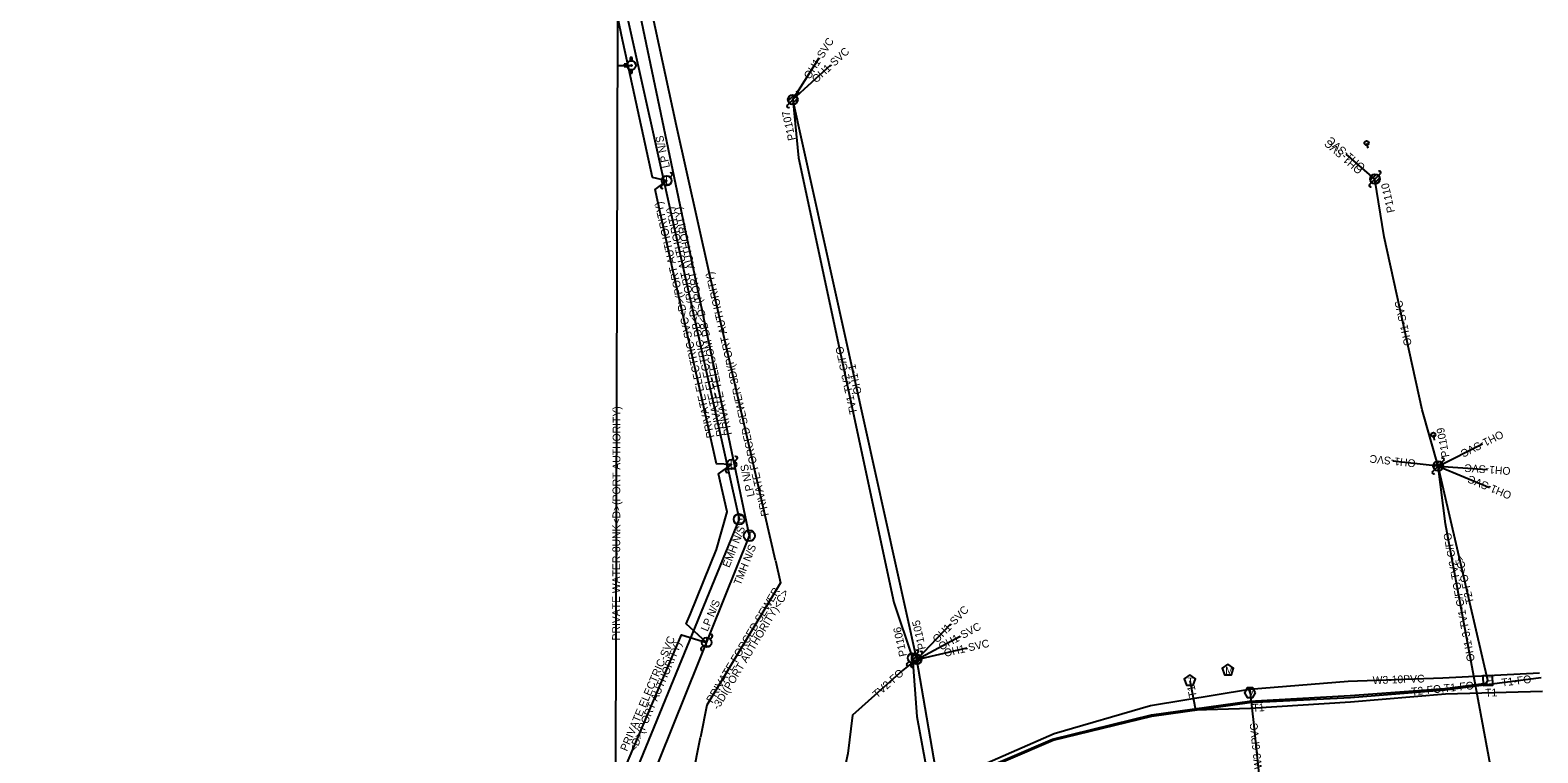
# Model space of a CAD drawing. Extents: x 2336688 to 2352634, y 362473 to 369571.
# Drawn here: x 2345105 to 2345883, y 367110 to 367482 of the extents above; entities that cross this region are included whole.
import ezdxf

# ---------------------------------------------------------------- set-up
doc = ezdxf.new("R2010")
doc.units = 0
for name, color, linetype in [('RD_EX_DV_Prop', 7, 'Continuous'), ('RD_EX_DV_TX_Prop', 7, 'Continuous'), ('RD_EX_RW', 7, 'Continuous'), ('RD_EX_RW_TX', 7, 'Continuous'), ('RD_HC_Data_Tic', 7, 'Continuous'), ('RD_PD_CstnLmt', 7, 'Continuous'), ('RD_PD_Final_TrvlWay', 7, 'Continuous'), ('RD_PD_PatLn4', 7, 'Continuous'), ('RD_SHT_ShtClip', 7, 'Continuous'), ('RD_Sketch1', 7, 'Continuous'), ('RD_Sketch2', 7, 'Continuous'), ('RD_Sketch5', 7, 'Continuous')]:
    doc.layers.add(name, color=color, linetype=linetype)

# ---------------------------------------------------------------- blocks, each defined once
blk = doc.blocks.new('GW')
at = {"layer": 'RD_HC_Data_Tic'}
blk.add_line((0, 0), (0, 5), dxfattribs=at)
blk.add_circle((0, 0), 2, dxfattribs=at)

msp = doc.modelspace()

# ---------------------------------------------------------------- linework, layer by layer
at = {"layer": 'RD_EX_RW_TX'}
msp.add_line((2345857.04, 367146.79), (2345831.39, 367257.27), dxfattribs=at)
for points in [[(2345400.86, 367609.96), (2345400.86, 367580.52), (2345476.19, 367221.38), (2345364.16, 366943.34), (2345117.95, 366720.57)], [(2345560.36, 367158.37), (2345561.17, 367156.84), (2345555.2, 367151.92), (2345529.41, 367128.95), (2345527.05, 367109.15), (2345521, 367081.68), (2345512.82, 367070.16), (2345492.13, 367039.11), (2345457.71, 366999.28), (2345443.39, 366979.23), (2345436.01, 366963.6), (2345427.31, 366951.13), (2345399.42, 366920.61), (2345372.17, 366875.98), (2345340.52, 366834.69)], [(2345399.69, 366921.53), (2345400.81, 366920.91), (2345403.09, 366921.35), (2345436.25, 366953.11), (2345452.55, 366965.66), (2345470.76, 366986.63), (2345499.17, 367023.99), (2345542.57, 367063.95), (2345586.06, 367096.71), (2345632.54, 367116.51), (2345683.64, 367129.17), (2345734.05, 367136.11), (2345786.05, 367139.04), (2345834.85, 367142.6), (2345856.07, 367145.42), (2345857.04, 367146.79)], [(2345400.81, 366920.91), (2345403.21, 366920.71), (2345436.7, 366952.69), (2345453.09, 366965.46), (2345471.44, 366986.29), (2345499.66, 367023.61), (2345543.05, 367063.34), (2345586.52, 367096.12), (2345632.95, 367115.99), (2345683.75, 367128.36), (2345734.17, 367135.46), (2345786.21, 367138.11), (2345835, 367141.95), (2345884.47, 367148.28)], [(2345703.35, 367146.8), (2345703.48, 367145.97), (2345706.2, 367131.66), (2345734.69, 367132.6), (2345786.23, 367135.82), (2345835.18, 367139.89), (2345885.18, 367141.35)]]:
    msp.add_lwpolyline(points, dxfattribs=at)
for points in [[(2345703.35, 367149.8), (2345700.5, 367147.73), (2345701.59, 367144.37), (2345705.11, 367144.37), (2345706.2, 367147.73)], [(2345859.44, 367149.38), (2345854.45, 367149.19), (2345854.64, 367144.19), (2345859.63, 367144.38)]]:
    msp.add_lwpolyline(points, close=True, dxfattribs=at)
msp.add_circle((2345476.19, 367221.38), 2.89, dxfattribs=at)
at = {"layer": 'RD_HC_Data_Tic'}
for p, q in [((2345496.21, 367445.35), (2345499.27, 367448.41)), ((2345496.86, 367444.23), (2345500.39, 367447.76)), ((2345497.98, 367443.58), (2345501.04, 367446.64)), ((2345500.39, 367447.76), (2345501.46, 367448.83)), ((2345495.8, 367443.17), (2345496.86, 367444.23)), ((2345435.34, 367406), (2345436.4, 367407.06)), ((2345796.4, 367404.44), (2345799.47, 367407.5)), ((2345797.05, 367403.32), (2345800.59, 367406.86)), ((2345798.17, 367402.67), (2345801.23, 367405.74)), ((2345800.59, 367406.86), (2345801.65, 367407.92)), ((2345430.74, 367401.4), (2345431.8, 367402.46)), ((2345795.99, 367402.26), (2345797.05, 367403.32)), ((2345468.78, 367259.84), (2345469.84, 367260.91)), ((2345828.98, 367256.62), (2345832.04, 367259.68)), ((2345829.63, 367255.5), (2345833.16, 367259.04)), ((2345833.16, 367259.04), (2345834.22, 367260.1)), ((2345464.18, 367255.25), (2345465.25, 367256.31)), ((2345828.56, 367254.44), (2345829.63, 367255.5)), ((2345830.75, 367254.85), (2345833.81, 367257.92)), ((2345455.96, 367168.17), (2345457.02, 367169.23)), ((2345451.36, 367163.57), (2345452.42, 367164.63)), ((2345560.1, 367157.02), (2345563.16, 367160.08)), ((2345560.74, 367155.9), (2345564.28, 367159.44)), ((2345561.86, 367155.25), (2345564.92, 367158.32)), ((2345562.13, 367160.14), (2345563.19, 367161.2)), ((2345564.28, 367159.44), (2345565.34, 367160.5)), ((2345557.53, 367155.54), (2345558.59, 367156.6)), ((2345559.68, 367154.84), (2345560.74, 367155.9))]:
    msp.add_line(p, q, dxfattribs=at)
for centre in [(2345498.63, 367446), (2345433.57, 367404.23), (2345798.82, 367405.09), (2345467.01, 367258.08), (2345831.39, 367257.27), (2345454.19, 367166.4), (2345560.36, 367158.37), (2345562.51, 367157.67)]:
    msp.add_circle(centre, 2.5, dxfattribs=at)
for centre, start, end in [((2345500.93, 367449.36), 315, 135), ((2345496.33, 367442.64), 135, 315), ((2345435.87, 367407.59), 315, 135), ((2345801.12, 367408.45), 315, 135), ((2345431.27, 367400.87), 135, 315), ((2345796.52, 367401.73), 135, 315), ((2345469.31, 367261.44), 315, 135), ((2345833.69, 367260.63), 315, 135), ((2345464.72, 367254.72), 135, 315), ((2345829.09, 367253.91), 135, 315), ((2345456.49, 367169.76), 315, 135), ((2345451.89, 367163.04), 135, 315), ((2345562.66, 367161.73), 315, 135), ((2345564.81, 367161.03), 315, 135), ((2345558.06, 367155.01), 135, 315), ((2345560.21, 367154.31), 135, 315)]:
    msp.add_arc(centre, 0.75, start, end, dxfattribs=at)
at = {"layer": 'RD_PD_Final_TrvlWay'}
for points in [[(2345391.05, 367609.96), (2345391.05, 367588.26), (2345470.9, 367229.85), (2345354.8, 366946.71), (2345105.35, 366734.78)], [(2345401.67, 367077.29), (2345441.14, 367170.24), (2345454.19, 367166.4), (2345443.56, 367175.95), (2345445.8, 367181.21), (2345459.27, 367214.27), (2345464.69, 367233.75), (2345460.36, 367253.32), (2345467.01, 367258.08), (2345459.23, 367258.41), (2345451.73, 367292.22), (2345436.86, 367357.49), (2345427.63, 367399.68), (2345433.57, 367404.23), (2345426.25, 367405.97), (2345410.24, 367479.19), (2345396.95, 367544.45)]]:
    msp.add_lwpolyline(points, dxfattribs=at)
msp.add_circle((2345470.9, 367229.85), 2.75, dxfattribs=at)
at = {"layer": 'RD_SHT_ShtClip'}
for p, q in [((2345498.63, 367446), (2345512.16, 367467.57)), ((2345498.63, 367446), (2345518.26, 367464)), ((2345562.51, 367157.67), (2345498.63, 367446)), ((2345798.82, 367405.09), (2345783.9, 367417.98)), ((2345831.39, 367257.27), (2345854.23, 367268.72)), ((2345831.39, 367257.27), (2345807.96, 367259.81)), ((2345831.39, 367257.27), (2345856.87, 367255.47)), ((2345831.39, 367257.27), (2345857.93, 367246.29)), ((2345562.51, 367157.67), (2345580.17, 367176.01)), ((2345562.51, 367157.67), (2345584.96, 367169.69)), ((2345562.51, 367157.67), (2345588.48, 367163.57)), ((2345597.31, 366958.44), (2345562.51, 367157.67))]:
    msp.add_line(p, q, dxfattribs=at)
for points in [[(2345498.63, 367446), (2345501.62, 367416), (2345550.78, 367186.95), (2345560.36, 367158.37)], [(2345831.39, 367257.27), (2345823.18, 367286.18), (2345803.52, 367375.4), (2345798.82, 367405.09)], [(2345873.97, 367029.36), (2345866.69, 367058.52), (2345835.13, 367227.45), (2345831.39, 367257.27)], [(2345560.36, 367158.37), (2345562.49, 367128.3), (2345588.55, 366987.28), (2345597.31, 366958.44)]]:
    msp.add_lwpolyline(points, dxfattribs=at)
at = {"layer": 'RD_Sketch2'}
for p, q in [((2345408.27, 367463.66), (2345415.35, 367463.61)), ((2345411.64, 367464.25), (2345411.63, 367463.1)), ((2345411.63, 367463.1), (2345413.1, 367463.09)), ((2345413.13, 367464.25), (2345411.64, 367464.25)), ((2345414.68, 367461.4), (2345414.68, 367459.6)), ((2345414.7, 367467.69), (2345414.7, 367465.83)), ((2345415.86, 367467.69), (2345414.7, 367467.69)), ((2345415.83, 367459.6), (2345415.84, 367461.36)), ((2345415.85, 367465.87), (2345415.86, 367467.69)), ((2345414.68, 367459.6), (2345415.83, 367459.6))]:
    msp.add_line(p, q, dxfattribs=at)
for points in [[(2345109.82, 366912.24), (2345406.89, 366960.68), (2345406.94, 366978.47), (2345408.67, 367610.14)], [(2345398.01, 366858.08), (2345417.9, 366904.52), (2345437.85, 366951.84), (2345449.04, 366972.91), (2345453.48, 366979.61), (2345468.15, 367001.19), (2345500.41, 367039.08), (2345511.67, 367048.37), (2345517.71, 367054.69), (2345536.56, 367071.08), (2345585.14, 367098.45), (2345633.32, 367119.57), (2345683.1, 367133.89), (2345734.03, 367142.31), (2345784.94, 367146.49), (2345833.73, 367148.15), (2345883.62, 367150.82)], [(2345734.3, 367142.33), (2345734.6, 367138.65), (2345736.14, 367125.25), (2345743.53, 367053.85), (2345754.56, 366998.53), (2345763.65, 366947.65), (2345773.38, 366898.37), (2345784.57, 366849.11), (2345798.12, 366787.05), (2345817.62, 366699.96), (2345828.5, 366650.59), (2345839.82, 366600.83), (2345850.62, 366551.62)]]:
    msp.add_lwpolyline(points, dxfattribs=at)
for points in [[(2345722.98, 367155.23), (2345720.08, 367153.12), (2345721.19, 367149.71), (2345724.77, 367149.71), (2345725.88, 367153.12)], [(2345737.23, 367140.48), (2345735.79, 367142.97), (2345732.9, 367142.97), (2345731.46, 367140.48), (2345732.9, 367137.98), (2345735.79, 367137.98)]]:
    msp.add_lwpolyline(points, close=True, dxfattribs=at)
for radius in [2.31, 0.289]:
    msp.add_circle((2345415.35, 367463.61), radius, dxfattribs=at)
for start, end in [(164.06396, 193.0312), (253.15713, 282.13345), (77.50342, 106.47974)]:
    msp.add_arc((2345415.35, 367463.61), 2.31, start, end, dxfattribs=at)
at = {"layer": 'RD_Sketch5'}
for points in [[(2345489.61, 367208.62), (2345476.65, 367265.53), (2345455.27, 367357.83), (2345438.59, 367432.47), (2345425.85, 367491.41), (2345412.89, 367556.22), (2345439.65, 367587.91), (2345527.62, 367601.55), (2345628.3, 367608.81), (2345689.77, 367613.3), (2345752.19, 367617.68), (2345783.03, 367619.1), (2345837.36, 367621.88), (2345858.01, 367622.94), (2345857.63, 367639.38)], [(2345489.61, 367208.62), (2345492.23, 367197.12), (2345454.33, 367134.01), (2345451.04, 367117.69)], [(2345388.31, 366866.23), (2345411.68, 366909.13), (2345430.85, 366961.88), (2345435.05, 366988.91), (2345438.45, 367037.33), (2345442.85, 367076.95), (2345451.04, 367117.69)]]:
    msp.add_lwpolyline(points, dxfattribs=at)

# ---------------------------------------------------------------- block references
at = {"layer": 'RD_HC_Data_Tic', "xscale": 0.5546771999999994}
for p, yscale, rotation in [((2345794.5, 367423.63), 0.5546771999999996, -166.5456153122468), ((2345828.91, 367273.36), 0.5546771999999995, -170.86461615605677)]:
    msp.add_blockref('GW', p, dxfattribs=dict(at, yscale=yscale, rotation=rotation))

# ---------------------------------------------------------------- texts
at = {"layer": 'RD_EX_DV_Prop'}
for s, rotation, p in [('PRIVATE ELECTRIC-SVC<D>(PORT AUTHORITY)', 102.55203, (2345458.22, 367272.2)), ('PRIVATE ELECTRIC-DB<D>(PORT AUTHORITY)', 102.55203, (2345463.33, 367273.01)), ('EMH N/S', 68.05424, (2345465.83, 367204.63)), ('PRIVATE ELECTRIC-SVC', 66.99176, (2345413.1, 367110.05)), ('<D>(PORT AUTHORITY)', 66.99176, (2345417.65, 367109.81))]:
    msp.add_text(s, height=4, rotation=rotation, dxfattribs=at).set_placement(p)
at = {"layer": 'RD_EX_DV_TX_Prop'}
for s, rotation, p in [('P1107', 102.49284, (2345500.15, 367425.41)), ('LP N/S', 102.49579, (2345435.32, 367411.26)), ('P1110', 102.42715, (2345809.09, 367388.23)), ('P1109', 100.58176, (2345837.21, 367262.13)), ('LP N/S', 102.49579, (2345478.99, 367241.93)), ('LP N/S', 66.99176, (2345454.65, 367171.76)), ('P1106', 102.11312, (2345557.47, 367159.56)), ('P1105', 102.49284, (2345567.28, 367163.1))]:
    msp.add_text(s, height=4, rotation=rotation, dxfattribs=at).set_placement(p)
at = {"layer": 'RD_EX_RW'}
for s, rotation, p in [('PRIVATE TELECOM-DB<D>(PORT AUTHORITY)', 102.57365, (2345467.3, 367273.58)), ('TMH N/S', 68.05424, (2345471.64, 367195.52)), ('T2-FO<C>', 103.06913, (2345849.81, 367186.79)), ('TV2-FO', 41.68548, (2345542.01, 367137.49)), ('T1-FO', 7.30844, (2345864.31, 367143.68)), ('T1', 100.76848, (2345706.94, 367138.48)), ('T2-FO,T1-FO', 5.83186, (2345817.73, 367139.06)), ('T1', 1.67488, (2345855.67, 367138.48)), ('T1', 3.57287, (2345735.74, 367130.66))]:
    msp.add_text(s, height=4, rotation=rotation, dxfattribs=at).set_placement(p)
at = {"layer": 'RD_EX_RW_TX'}
for height, p in [(4.12, (2345474.86, 367219.32)), (3.75, (2345702.12, 367144.57))]:
    msp.add_text('T', height=height, dxfattribs=at).set_placement(p)
msp.add_text('F', height=4, rotation=2.17061, dxfattribs=at).set_placement((2345855.98, 367144.75))
at = {"layer": 'RD_HC_Data_Tic'}
for p in [(2345432.76, 367402.29), (2345466.2, 367256.14), (2345453.38, 367164.46)]:
    msp.add_text('L', height=4, rotation=360, dxfattribs=at).set_placement(p)
msp.add_text('O', height=4, dxfattribs=at).set_placement((2345559.07, 367156.37))
at = {"layer": 'RD_PD_CstnLmt'}
for s, rotation, p in [('PRIVATE WATER-8UNK<D>(PORT AUTHORITY)', 89.85895, (2345409.46, 367167.4)), ('W3-10PVC', 1.95236, (2345797.7, 367144.92)), ('W3-6PVC', 95.90661, (2345740.62, 367101.44))]:
    msp.add_text(s, height=4, rotation=rotation, dxfattribs=at).set_placement(p)
at = {"layer": 'RD_PD_Final_TrvlWay'}
msp.add_text('E', height=3.93, dxfattribs=at).set_placement((2345469.71, 367227.89))
at = {"layer": 'RD_PD_PatLn4'}
for s, rotation, p in [('OH1-SVC', 57.89747, (2345507.36, 367456.15)), ('OH1-SVC', 42.52363, (2345510.64, 367454.3)), ('OH1-SVC', 139.17197, (2345792.85, 367410.25)), ('OH1-SVC', 139.17197, (2345794.16, 367411.76)), ('OH1-SVC', 102.42715, (2345817.85, 367319.67)), ('TV1,TV2-C/FO', 102.11312, (2345531.91, 367284.38)), ('OH1-1', 102.49284, (2345534.2, 367294.68)), ('OH1-SVC', 206.62884, (2345863.78, 367275.75)), ('OH1-SVC', 173.81688, (2345819.94, 367260.52)), ('OH1-SVC', 175.9603, (2345868.82, 367256.63)), ('OH1-SVC', 157.51993, (2345869.61, 367243.62)), ('OH1-3,TV1-C/FO,TV2-C/FO', 100.58176, (2345850.34, 367156.93)), ('OH1-SVC', 46.08021, (2345573.13, 367165.82)), ('OH1-SVC', 28.18027, (2345575.12, 367162.16)), ('OH1-SVC', 12.80643, (2345577.06, 367158.93))]:
    msp.add_text(s, height=4, rotation=rotation, dxfattribs=at).set_placement(p)
at = {"layer": 'RD_Sketch1'}
for s, rotation, p in [('PRIVATE FORCED SEWER-3DI(PORT AUTHORITY)', 102.97545, (2345486.36, 367231.92)), ('PRIVATE FORCED SEWER', 59.00331, (2345457.15, 367134.83)), ('-3DI(PORT AUTHORITY)<C>', 59.00331, (2345460.2, 367131.37))]:
    msp.add_text(s, height=4, rotation=rotation, dxfattribs=at).set_placement(p)
at = {"layer": 'RD_Sketch2'}
for s, p in [('M', (2345721.61, 367150.19)), ('V', (2345733.13, 367138.6))]:
    msp.add_text(s, height=3.75, dxfattribs=at).set_placement(p)

doc.saveas('drawing.dxf')
